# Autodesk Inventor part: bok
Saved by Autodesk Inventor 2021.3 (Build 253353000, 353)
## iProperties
Created: 2023-02
Part Number: bok
Material: Generic
Document SubType Name: Modeling
Designer: AdminForWorker
Density: 1 g/cm^3
Appearance: Default
Title: bok
Author: AdminForWorker
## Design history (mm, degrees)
feature "Body1"
body "Solid1"
